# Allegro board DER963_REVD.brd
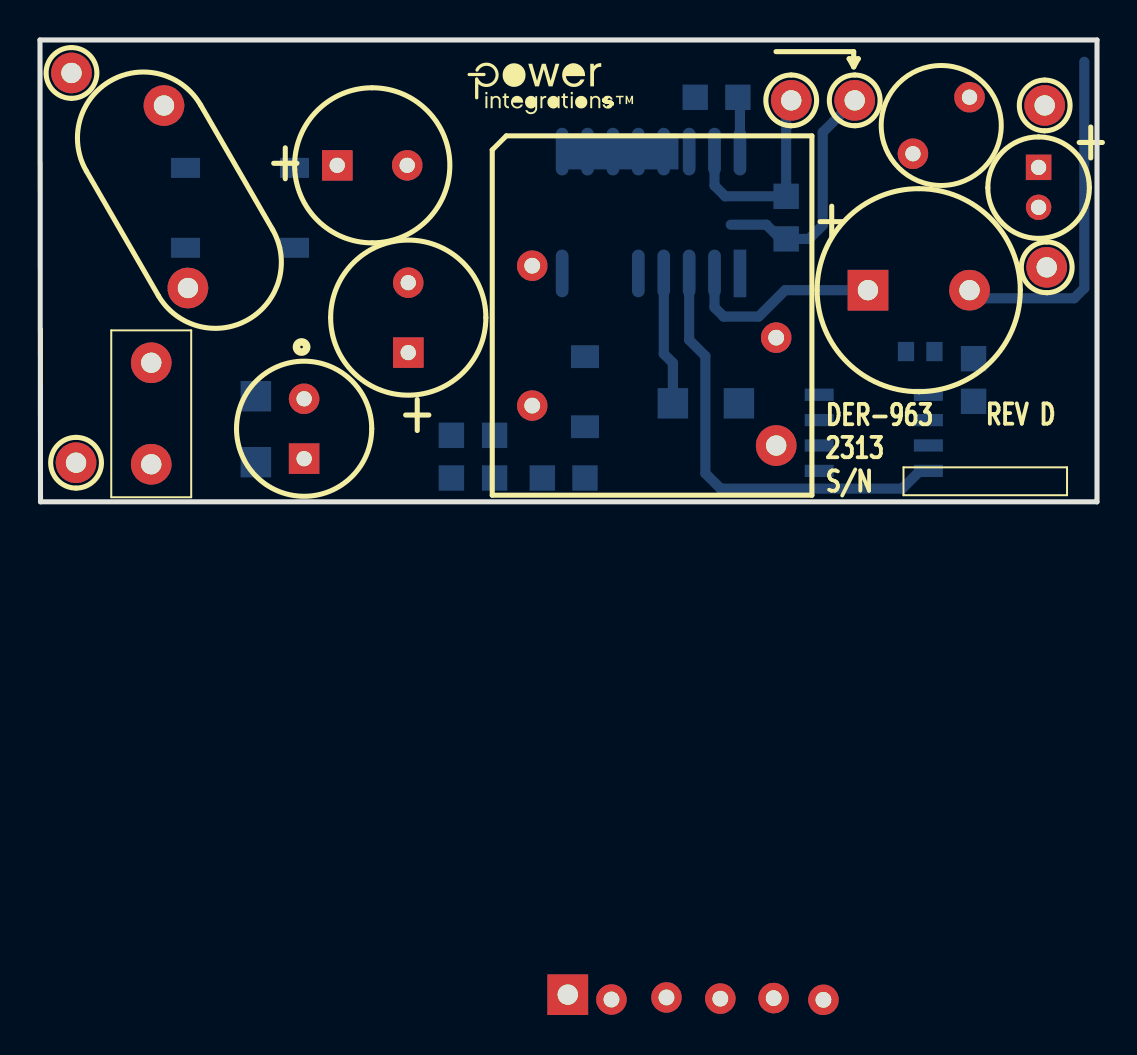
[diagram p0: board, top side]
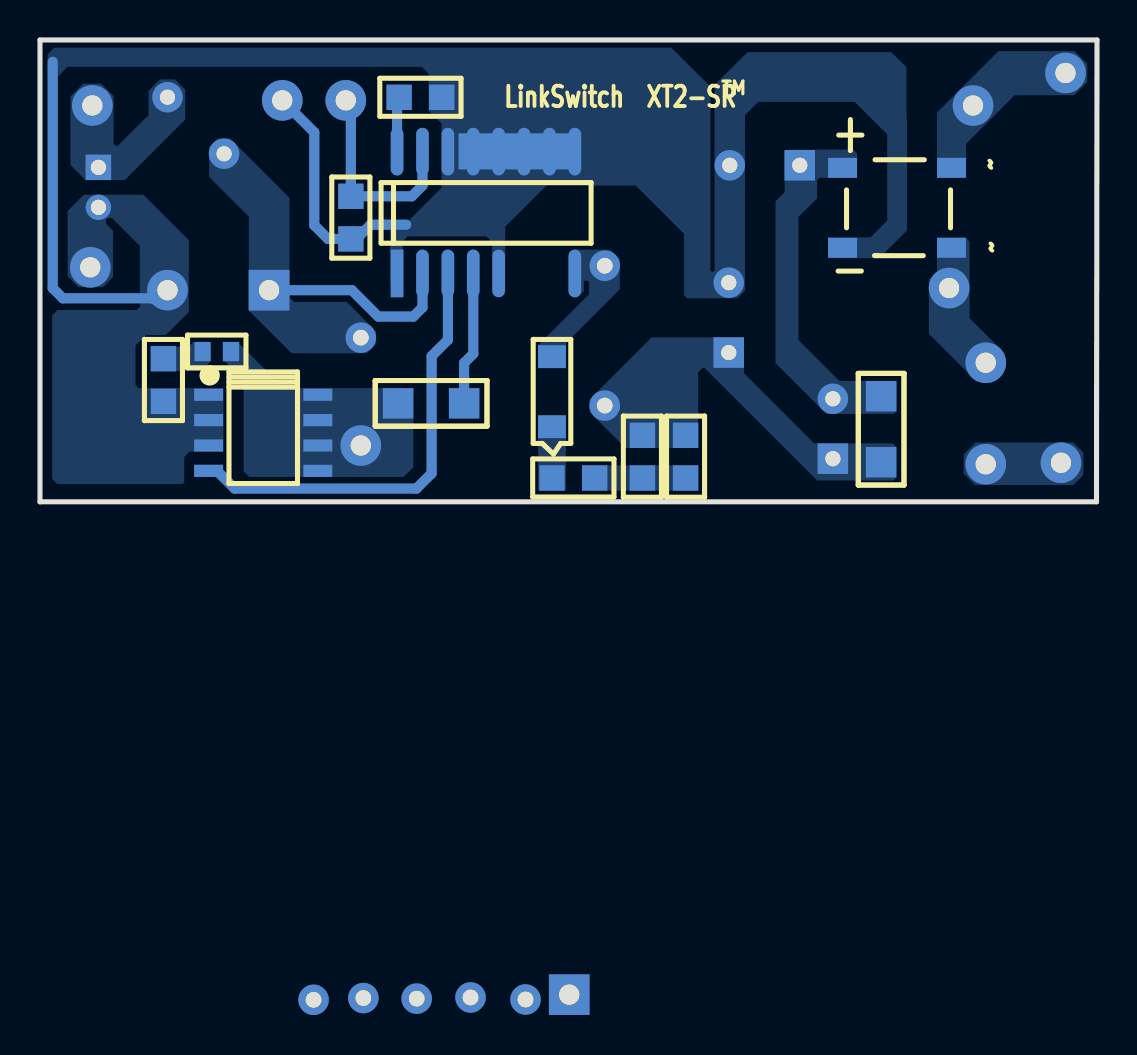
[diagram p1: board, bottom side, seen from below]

Outline 52.86 x 23.11 mm; copper layers: TOP, BOTTOM. Coordinates in mm from the lower left corner of the outline.
Outline path: 0,23.11 0.03,0.25 0.03,0 52.86,0 52.86,23.11 0,23.11

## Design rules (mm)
constraint set DEFAULT: min track width 0.508

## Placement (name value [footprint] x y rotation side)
BR1  ABS210-13  [PISMD_SOPA-4]  12.73 16.71 90 bottom
C1  5.6 uF  [PIPOLCAPCYLD315LS138D030]  14.86 16.84 0 top
C2  5.6 uF  [PIPOLCAPCYLD315LS138D030]  18.42 7.47 90 top
C3  1000 pF  [PISMC0805]  22.73 1.19 90 bottom
C4  4.7 uF  [PISMC0805]  32.77 20.24 0 bottom
C5  2.2 uF  [PISMC0805]  37.31 13.16 90 bottom
C6  1000 pF  [PISMC0603]  43.31 7.52 0 bottom
C7  1000 uF  [PIPOLCAPCYLD400LS200040]  41.4 10.59 0 top
C8  100  uF  [PIPOLCAPCLYD200LS80030]  49.94 16.74 270 top
D1  S1MLHRVG  [PI_SM_SOD-123_12]  27.25 3.76 90 bottom
F1  1 A  [PI_RST_MICROFUSE]  5.56 1.88 90 top
GND  GND  [PITPKEYSTONE100X100]  50.34 11.73 0 top
GND_TP  BLK  [PITPKEYSTONE100X100]  40.74 20.09 0 top
L  BLK  [PITPKEYSTONE100X100]  1.8 1.96 0 top
L1  100 uH  [PI_CHOKE_RL5480-2_D2]  13.21 2.16 90 top
L2  1.7 uH  [PICHOKE6MM2PIN4MMLSD030]  43.65 17.42 315 top
N  WHT  [PITPKEYSTONE100X100]  1.57 21.46 0 top
NOREF  -  []  0.1 23.11 0 top
NOREF#2  -  []  -239.7 -151.03 0 top
NOREF#3  -  []  20.83 21.87 0 top
NOREF#4  -  []  0.03 0.25 90 top
NOREF#5  -  []  -161.88 47.99 0 top
Q1  AO4264E  [PISMSO8]  44.42 5.36 270 bottom
R1  10 k  [PISMR1206]  10.79 5.28 270 bottom
R2  240 k  [PISMR0805]  20.57 1.19 90 bottom
R3  62  [PISMR0805]  25.12 1.19 0 bottom
R4  10  [PISMR0805]  46.69 5.03 90 bottom
R5  47  [PISMR1206]  34.95 4.93 180 bottom
RV1  275 Vac  [PIDISC500X225LS335X140040]  6.2 19.83 300 top
T1  EE16  [PIBOBBINEE1610P4X6]  24.62 15.32 0 top
U1  LNK3771D-H003  [PI_SMD_SO_14-16P_SHORT9-14]  35 11.43 180 bottom
UNK+UVCC  WHT  [PITPKEYSTONE100X100]  37.57 20.09 0 top
V+  RED  [PITPKEYSTONE100X100]  50.24 19.84 0 top

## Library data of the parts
BR1 = DIODE BRIDGE_+~~-: alternate symbols: (pismd_SOPA-4a,pi_sm_soic4_slot)
C1 C2 = CAP POL: alternate symbols: (pipolcapcyld315ls138d030h)
C3-C6 = CAP NP
C7 = CAP POL: alternate symbols: (pipolcapclyd395x630ls200030h)
C8 = CAP POL: alternate symbols: (pipolcapclyd200ls80030h)
D1 = DIODE
F1 = FUSE: alternate symbols: (pirstmicrofusehoz)
GND N UNK+UVCC V+ = TESTPOINT
GND_TP L = TESTPOINT: alternate symbols: (TP_TH_CR2_D1_1)
L1 = INDUCTOR_dot2: alternate symbols: (pi_choke_RL5480-2H_d2)
L2 = INDUCTOR
Q1 = FET_P_SGD_123_4_5678
R1 R2 R4 R5 = R
R3 = R: alternate symbols: (Unisem_RMCF0805UL)
RV1 = VARISTOR
T1 = BEE16_10P_4x6/GENERIC
U1 = LNKXT2-SR2aL

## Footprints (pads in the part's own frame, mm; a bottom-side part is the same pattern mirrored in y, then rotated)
PI_CHOKE_RL5480-2_D2
  rect 1.524x1.524 hole 0.762: 1(0,0)
  round 1.524 hole 0.762: 2(2.997,0)
PI_RST_MICROFUSE
  round 2.032 hole 1.016: 1(0,0) 2(5.08,0)
PI_SM_SOD-123_12
  rect 1.143x1.397 smd: 1(0,0) 2(3.505,0)
PI_SMD_SO_14-16P_SHORT9-14
  rect 0.635x2.388 smd: 1(0,0)
  oval 0.635x2.388 smd: 2(1.27,0) 3(2.54,0) 4(3.81,0) 5(5.08,0) 8(8.89,0) 9(8.89,6.096) 10(7.62,6.096) 11(6.35,6.096) 12(5.08,6.096) 13(3.81,6.096) 14(2.54,6.096) 15(1.27,6.096) 16(0,6.096)
PIBOBBINEE1610P4X6
  rect 2.032x2.032 hole 1.016: 1(1.778,-39.98)
  round 1.524 hole 0.787: 2(0,-3.5) 3(3.962,-40.223) 4(0,-10.5) 6(12.073,-40.152) 7(12.2,-7.099) 8(14.562,-40.239) 9(9.406,-40.18) 10(6.713,-40.122)
  round 2.032 hole 1.016: 5(12.2,-12.499)
PICHOKE6MM2PIN4MMLSD030
  round 1.524 hole 0.762: 1(0,0) 2(0,4)
PIDISC500X225LS335X140040
  round 2.032 hole 1.016: 1(0,0) 2(8.509,-3.531)
PIPOLCAPCLYD200LS80030
  rect 1.27x1.27 hole 0.762: 1(0,0)
  round 1.27 hole 0.762: 2(2,0)
PIPOLCAPCYLD315LS138D030
  rect 1.524x1.524 hole 0.762: 1(0,0)
  round 1.524 hole 0.762: 2(3.5,0)
PIPOLCAPCYLD400LS200040
  rect 2.032x2.032 hole 1.016: 1(0,0)
  round 2.032 hole 1.016: 2(5.08,0)
PISMC0603
  rect 0.813x0.965 smd: 1(0,0) 2(1.422,0)
PISMC0805
  rect 1.27x1.27 smd: 1(0,0) 2(2.134,0)
PISMD_SOPA-4
  rect 1.001x1.45 smd: 1(0,0) 2(0,-5.45) 3(-4,-5.45) 4(-4,0)
PISMR0805
  rect 1.27x1.27 smd: 1(0,0) 2(2.134,0)
PISMR1206
  rect 1.524x1.524 smd: 1(0,0) 2(3.302,0)
PISMSO8
  rect 0.61x1.448 smd: 1(0,0) 2(1.27,0) 3(2.54,0) 4(3.81,0) 5(3.81,5.461) 6(2.54,5.461) 7(1.27,5.461) 8(0,5.461)
PITPKEYSTONE100X100
  round 2.032 hole 1.016: 1(0,0)

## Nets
V+: C8.1 L2.2 V+.1
N2618494: BR1.1 C1.1 L1.2 R1.1
N2618510: C2.1 C3.2 L1.1 R1.2 R2.2 T1.4
N2618826: C3.1 R2.1 R3.1
N2618854: C6.2 R4.2
N2618858: BR1.4 C1.2 C2.2 C4.1 C5.1 C7.2 C8.2 GND.1 GND_TP.1 Q1.1 Q1.2 Q1.3(S3) R4.1 U1.1 U1.5 U1.9 U1.10 U1.11 U1.12 U1.13 U1.14
N2618994: D1.1 R3.2
N2618998: D1.2 T1.2 U1.8
N2619088: Q1.4 U1.3
N2626861: BR1.2 N.1 RV1.1
N11228917: BR1.3 F1.2 RV1.2
N11238573: C7.1 L2.1 T1.7 U1.2
N11247136: C6.1 Q1.5 Q1.6 Q1.7 Q1.8 R5.1 T1.5
N11280302: F1.1 L.1
N11283147: R5.2 U1.4
N11283765: C4.2 U1.16
N11284197: C5.2 U1.15 UNK+UVCC.1

Pads without a net: T1 1 3 6 8 9 10

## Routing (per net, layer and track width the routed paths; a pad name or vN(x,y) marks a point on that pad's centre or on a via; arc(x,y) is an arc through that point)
N2618858: length 29.5
  BOTTOM w0.508: GND_TP.1 39.14,18.49 39.14,13.84 38.46,13.16 C5.1 37.03,13.16 36.32,13.87 34.54,13.87 ; 52.22,22.02 52.22,10.69 51.71,10.19 47.19,10.19 47.14,10.13 46.41,10.13
N2619088: length 22.2
  BOTTOM w0.508: Q1.4 44.01,1.55 43.12,0.66 34.04,0.66 33.27,1.42 33.27,7.29 32.46,8.1 U1.3
N11238573: length 9.6
  BOTTOM w0.508: U1.2 33.73,9.73 34.19,9.27 35.94,9.27 37.26,10.59 40.87,10.59
N11283147: length 6.7
  BOTTOM w0.508: 31.65,4.93 31.65,6.95 31.19,7.41 U1.4
N11283765: length 2.8
  BOTTOM w0.508: C4.2 35,20.14 U1.16
N11284197: length 10.4
  BOTTOM w0.508: UNK+UVCC.1 37.31,19.84 C5.2 34.26,15.29 33.73,15.82 U1.15

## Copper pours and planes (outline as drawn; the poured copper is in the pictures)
V+ on BOTTOM: 49.17,17.91 49.17,20.31 49.79,20.93 50.7,20.93 51.33,20.29 51.33,16.85 50.58,16.1 48.62,16.1 45.59,19.13 45.59,20.62 46.11,21.14 46.86,21.14 47.43,20.57 47.43,19.35 48.71,18.07 48.71,18.07 48.95,17.82 49.08,17.82
N2618494 on BOTTOM: 12.19,17.63 15.47,17.63 15.62,17.48 15.62,15.49 16.08,15.04 16.08,6.94 13.54,4.4 10.16,4.4 10.01,4.55 10.01,5.84 10.01,5.84 10.01,6.03 10.02,6.05 12.88,6.05 14.94,8.1 14.94,14.25 14,15.19 14,16.1 13.89,16.21 12.18,16.21 12.18,16.21 12,16.21 12,17.44
N2618510 on BOTTOM: 14.14,2.93 17.65,6.44 17.65,8.23 22.27,8.23 25.38,5.12 25.38,4.5 23.58,2.7 19.94,2.7 19.94,2.7 19.94,6.48 19.74,6.69 19.62,6.69 13.99,1.07 10.19,1.07 10.03,1.22 10.03,2.75 10.21,2.93
N2618826 on BOTTOM: 25.75,0.56 25.75,1.83 19.94,1.83 19.94,1.82 19.94,0.56 19.94,0.56
N2618854 on BOTTOM: 44.35,7.01 44.81,6.55 47.32,6.55 47.32,7.7 47.26,7.76 45.43,7.76 45.19,8 44.4,8 44.35,7.95
N2618858 on BOTTOM (solid shape): 31.93,16.64 26.14,16.64 26.14,18.44 31.93,18.44
N2618858 on BOTTOM: 43.69,2.53 43.7,2.52 45.36,2.52 45.64,2.24 45.64,0.99 45.75,0.89 51.98,0.89 52.25,1.16 52.25,9.32 51.97,9.6 48.03,9.6 47.85,9.78 47.85,10.13 47.87,10.15 47.87,12.81 49.25,14.2 49.48,14.2 49.56,14.12 49.56,13.92 49.2,13.56 49.2,11.25 49.71,10.74 50.93,10.74 51.47,11.29 51.47,14.55 50.66,15.37 47.69,15.37 45.42,13.09 45.42,9.5 46.57,8.34 47.56,8.34 48.08,7.82 48.08,5.84 47.93,5.69 43.69,5.69
N2618858 on BOTTOM: 35.36,10.85 34.67,10.85 34.72,10.9 34.72,13.03 34.47,13.28 30.53,13.28 30.25,13 30.25,10.57 30.05,10.36 29.77,10.36 29.59,10.54 29.59,13.77 27.53,15.82 23.06,15.82 20.65,13.41 20.65,10.34 20.5,10.19 17.98,10.19 17.6,10.57 17.6,19.35 16.94,20.02 12.12,20.02 10.49,18.39 10.49,14.07 11.33,13.23 13.43,13.23 13.45,13.21 13.45,12.21 13.43,12.19 10.9,12.19 9.5,13.59 9.5,19.13 9.52,19.15 9.52,21.74 10.29,22.5 17.48,22.5 19.13,20.85 19.13,11.58 19.2,11.51 19.25,11.51 19.33,11.58 19.33,20.78 21.29,22.73 52.15,22.73 52.48,22.4 52.48,21.39 52.25,21.16 52.1,21.16 51.49,21.77 33.76,21.77 33.43,21.44 33.43,19.58 32.89,19.05 32.89,19.04 32.78,18.93 32.78,15.71 34.39,14.1 34.98,14.1 35.36,13.72
N2618994 on BOTTOM: 27.94,4.33 26.56,4.33 26.56,0.57 27.94,0.57
N2618998 on BOTTOM: 26.16,12.62 26.42,12.37 26.42,10.41 26.24,10.24 25.96,10.24 25.67,10.53 25.67,11 25.6,11.07 25.48,11.07 25.4,10.99 25.4,10.38 27.95,7.83 27.95,6.69 26.56,6.69 26.56,6.85 26.56,7.94 23.86,10.63 23.86,12.15 24.33,12.62
N2626861 on BOTTOM: 4.93,22.56 8,19.48 8,16.28 8,16.21 6.55,16.21 6.55,16.22 6.55,17.91 4.11,20.35 1.15,20.35 0.49,21.01 0.49,21.92 1.12,22.56
N11228917 on BOTTOM: 5.26,6.02 6.02,6.02 8.41,8.41 8.41,11.13 8,11.53 8,13.21 6.55,13.21 6.38,13.04 6.38,9.19 4.62,7.44 4.62,6.65
N11238573 on BOTTOM: 36.52,7.44 36.05,7.9 36.05,8.53 37.53,10.01 40.16,10.01 40.38,10.23 40.38,15.22 43.35,18.18 43.99,18.18 44.4,17.77 44.4,16.26 42.42,14.27 42.42,9.57 40.28,7.44
N11247136 on BOTTOM: 42.67,1.52 42.39,1.24 34.67,1.24 34.19,1.73 34.19,5.69 40.67,5.69 42.93,7.95 43.51,7.95 43.66,7.8 43.66,7.09 42.67,6.1
N11280302 on BOTTOM: 1.19,0.84 6.09,0.84 6.66,1.41 6.66,2.38 6.07,2.97 1.19,2.97 0.68,2.46 0.68,1.35

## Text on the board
Ref Des/Silkscreen Bottom: TM | LinkSwitch  XT2-SR
Ref Des/Silkscreen Top: 2313 | DER-963 | S/N | REV D
User.5: 14.  FAB HOUSE LOGO,DATE CODE TO BE IN SILK SCREEN ONLY.DO NOT USE COPPER. | 13.  MATERIAL FR4 COPPER 2oz THICKNESS 0.062" | DELETE THESE PINS
User.8: FIGURE | FINISHED_SIZE | 30.0 | 31.0 | 40.0 | DRILL CHART: TOP to BOTTOM | ALL UNITS ARE IN MILS | TOLERANCE_DRILL | +3.0/-3.0 | PLATED | QTY | 10 | 8 | 14
